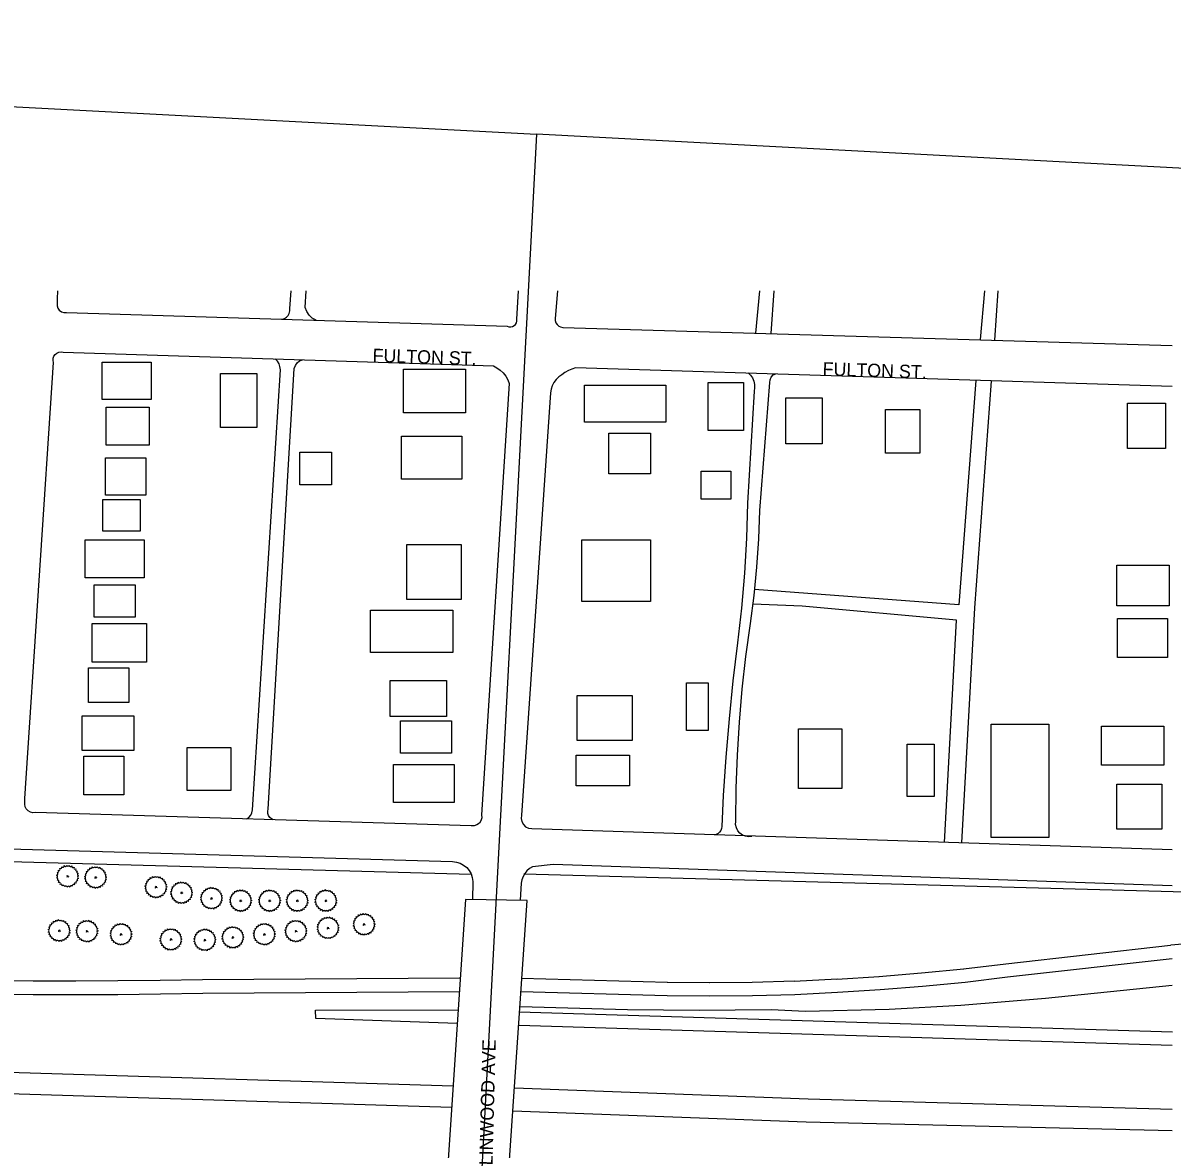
# Model space of a CAD drawing. Extents: x -9648 to 41057, y -12373 to 40276.
# Drawn here: x 13685 to 14546, y -5099 to -4256 of the extents above; entities that cross this region are included whole.
import ezdxf

# ---------------------------------------------------------------- set-up
doc = ezdxf.new("R2010")
doc.units = 0
for name, color, linetype in [('Default', 7, 'Continuous'), ('SC_Scratch1', 7, 'Continuous'), ('SH_Data', 7, 'Continuous')]:
    doc.layers.add(name, color=color, linetype=linetype)

# ---------------------------------------------------------------- blocks, each defined once
blk = doc.blocks.new('15_PIN')
at = {"layer": 'Default'}
for p, q in [((-2.8, 0), (2.8, 0)), ((0, 2.8), (0, -2.8))]:
    blk.add_line(p, q, dxfattribs=at)
for centre, start, end in [((-25.5, 4.5), 275.99, 64.01), ((-25.9, -1.5), 289.3234, 77.3433), ((-23.8, 10.3), 262.6567, 50.6766), ((-20.8, 15.5), 249.3234, 37.3433), ((-16.7, 19.8), 235.99, 24.01), ((-11.6, 23.2), 222.6567, 10.6766), ((-6, 25.2), 209.3234, 357.3433), ((0, 25.9), 195.99, 344.01), ((6, 25.2), 182.6567, 330.6766), ((11.6, 23.2), 169.3234, 317.3433), ((16.7, 19.8), 155.99, 304.01), ((20.8, 15.5), 142.6567, 290.6766), ((23.8, 10.3), 129.3234, 277.3433), ((25.5, 4.5), 115.99, 264.01), ((25.9, -1.5), 102.6567, 250.6766), ((-24.8, -7.4), 302.6567, 90.6766), ((-22.4, -13), 315.99, 104.01), ((-18.8, -17.8), 329.3234, 117.3433), ((-14.2, -21.6), 342.6567, 130.6766), ((-8.9, -24.3), 355.99, 144.01), ((-3, -25.7), 9.3234, 157.3433), ((3, -25.7), 22.6567, 170.6766), ((8.9, -24.3), 35.99, 184.01), ((14.2, -21.6), 49.3234, 197.3433), ((18.8, -17.8), 62.6567, 210.6767), ((22.4, -13), 75.99, 224.01), ((24.8, -7.4), 89.3234, 237.3433)]:
    blk.add_arc(centre, 3.05, start, end, dxfattribs=at)

msp = doc.modelspace()

# ---------------------------------------------------------------- linework, layer by layer
at = {"layer": 'SC_Scratch1'}
for p, q in [((12492.94, -4255.51), (14069.83, -4338.81)), ((14069.83, -4338.81), (13988.59, -5876.66)), ((14069.83, -4338.81), (13988.59, -5876.66)), ((14069.83, -4338.81), (13988.59, -5876.66)), ((15927.4, -4436.94), (14069.83, -4338.81))]:
    msp.add_line(p, q, dxfattribs=at)
at = {"layer": 'SH_Data'}
for p, q in [((13710.88, -4456.26), (13710.48, -4462.06)), ((13885.08, -4469.46), (13885.88, -4456.26)), ((13896.48, -4468.66), (13897.08, -4456.26)), ((14055.08, -4477.46), (14056.28, -4456.26)), ((14085.48, -4456.26), (14083.88, -4476.86)), ((14234.28, -4487.86), (14237.08, -4456.26)), ((14247.68, -4456.26), (14245.48, -4488.16)), ((14405.48, -4456.26), (14402.28, -4492.76)), ((14413.28, -4493.06), (14415.68, -4456.26)), ((13710.48, -4462.06), (13710.68, -4465.46)), ((13710.68, -4465.46), (13710.58, -4467.36)), ((13710.58, -4467.36), (13711.08, -4469.26)), ((13897.58, -4471.76), (13896.48, -4468.66)), ((13711.08, -4469.26), (13712.18, -4470.76)), ((13712.18, -4470.76), (13713.78, -4471.96)), ((13713.78, -4471.96), (13715.58, -4472.46)), ((13715.58, -4472.46), (13717.48, -4472.46)), ((13717.48, -4472.46), (14047.88, -4482.66)), ((13879.08, -4477.46), (13880.88, -4476.96)), ((13880.88, -4476.96), (13882.38, -4475.96)), ((13882.38, -4475.96), (13883.68, -4474.66)), ((13883.68, -4474.66), (13884.58, -4473.06)), ((13884.58, -4473.06), (13885.08, -4471.26)), ((13885.08, -4471.26), (13885.08, -4469.46)), ((13899.38, -4474.46), (13897.58, -4471.76)), ((13901.78, -4476.66), (13899.38, -4474.46)), ((13904.58, -4478.26), (13901.78, -4476.66)), ((14055.08, -4478.86), (14055.08, -4477.46)), ((14083.88, -4476.86), (14083.88, -4478.46)), ((14047.88, -4482.66), (14049.18, -4483.06)), ((14049.18, -4483.06), (14050.58, -4483.16)), ((14050.58, -4483.16), (14051.88, -4482.86)), ((14051.88, -4482.86), (14053.08, -4482.26)), ((14053.08, -4482.26), (14054.08, -4481.36)), ((14054.08, -4481.36), (14054.78, -4480.16)), ((14054.78, -4480.16), (14055.08, -4478.86)), ((14083.88, -4478.46), (14084.38, -4480.06)), ((14084.38, -4480.06), (14085.28, -4481.46)), ((14085.28, -4481.46), (14086.48, -4482.56)), ((14086.48, -4482.56), (14087.88, -4483.26)), ((14087.88, -4483.26), (14089.48, -4483.66)), ((14089.48, -4483.66), (14546.08, -4497.06)), ((13709.18, -4503.76), (13710.38, -4502.76)), ((13710.38, -4502.76), (13711.88, -4502.06)), ((13711.88, -4502.06), (13713.48, -4501.86)), ((13713.48, -4501.86), (13715.08, -4502.06)), ((13715.08, -4502.06), (14037.48, -4512.46)), ((13686.28, -4836.46), (13707.88, -4509.86)), ((13707.58, -4508.26), (13707.68, -4506.66)), ((13707.88, -4509.86), (13707.58, -4508.26)), ((13707.68, -4506.66), (13708.18, -4505.16)), ((13708.18, -4505.16), (13709.18, -4503.76)), ((13875.68, -4508.86), (13874.08, -4507.16)), ((13876.88, -4510.76), (13875.68, -4508.86)), ((13877.58, -4512.96), (13876.88, -4510.76)), ((13888.28, -4514.26), (13889.08, -4512.06)), ((13889.08, -4512.06), (13890.38, -4510.06)), ((13890.38, -4510.06), (13892.28, -4508.66)), ((13892.28, -4508.66), (13894.48, -4507.86)), ((13856.88, -4845.06), (13877.88, -4515.26)), ((13868.68, -4844.46), (13888.28, -4514.26)), ((13877.88, -4515.26), (13877.58, -4512.96)), ((14037.48, -4512.46), (14040.18, -4513.86)), ((14040.18, -4513.86), (14042.68, -4515.56)), ((14042.68, -4515.56), (14044.88, -4517.66)), ((14044.88, -4517.66), (14046.78, -4520.16)), ((14046.78, -4520.16), (14048.28, -4522.76)), ((14086.48, -4520.66), (14084.48, -4522.66)), ((14088.68, -4519.06), (14086.48, -4520.66)), ((14091.08, -4517.36), (14088.68, -4519.06)), ((14093.68, -4515.96), (14091.08, -4517.36)), ((14096.28, -4514.76), (14093.68, -4515.96)), ((14099.08, -4513.86), (14096.28, -4514.76)), ((14546.08, -4527.86), (14099.08, -4513.86)), ((14228.38, -4517.56), (14230.18, -4519.36)), ((14230.18, -4519.36), (14231.58, -4521.46)), ((14244.88, -4522.76), (14245.78, -4520.76)), ((14245.78, -4520.76), (14247.18, -4519.16)), ((14247.18, -4519.16), (14249.18, -4518.26)), ((14049.28, -4525.66), (14028.68, -4848.86)), ((14048.28, -4522.76), (14049.28, -4525.66)), ((14081.58, -4527.36), (14080.78, -4529.96)), ((14082.88, -4524.86), (14081.58, -4527.36)), ((14084.48, -4522.66), (14082.88, -4524.86)), ((14231.58, -4521.46), (14232.58, -4523.76)), ((14232.58, -4523.76), (14233.18, -4526.26)), ((14233.28, -4528.76), (14232.88, -4531.26)), ((14233.18, -4526.26), (14233.28, -4528.76)), ((14237.28, -4620.66), (14244.68, -4524.86)), ((14244.68, -4524.86), (14244.88, -4522.76)), ((14399.08, -4523.46), (14386.28, -4691.46)), ((14398.28, -4693.66), (14410.68, -4523.76)), ((14080.28, -4532.66), (14058.48, -4849.06)), ((14080.78, -4529.96), (14080.28, -4532.66)), ((14232.88, -4531.26), (14227.88, -4615.26)), ((14227.88, -4615.26), (14227.18, -4641.46)), ((14236.48, -4641.96), (14237.28, -4620.66)), ((14227.18, -4641.46), (14225.78, -4667.66)), ((14234.98, -4663.16), (14236.48, -4641.96)), ((14232.88, -4684.36), (14234.98, -4663.16)), ((14225.78, -4667.66), (14223.48, -4693.86)), ((14230.08, -4705.46), (14232.88, -4684.36)), ((14386.28, -4691.46), (14233.28, -4679.86)), ((14268.98, -4692.46), (14231.98, -4691.06)), ((14384.68, -4702.86), (14268.98, -4692.46)), ((14223.48, -4693.86), (14220.48, -4719.86)), ((14388.68, -4869.86), (14398.28, -4693.66)), ((14226.78, -4730.06), (14230.08, -4705.46)), ((14375.68, -4869.46), (14384.68, -4702.86)), ((14220.48, -4719.86), (14216.98, -4748.36)), ((14223.98, -4754.66), (14226.78, -4730.06)), ((14216.98, -4748.36), (14214.08, -4776.96)), ((14221.88, -4779.36), (14223.98, -4754.66)), ((14214.08, -4776.96), (14211.58, -4805.56)), ((14220.38, -4804.06), (14221.88, -4779.36)), ((14219.38, -4828.86), (14220.38, -4804.06)), ((14211.58, -4805.56), (14209.68, -4834.26)), ((14219.08, -4853.66), (14219.38, -4828.86)), ((13686.28, -4840.66), (13686.28, -4836.46)), ((14209.68, -4834.26), (14208.68, -4857.46)), ((13686.58, -4842.66), (13686.28, -4840.66)), ((13687.48, -4844.36), (13686.58, -4842.66)), ((13688.88, -4845.86), (13687.48, -4844.36)), ((13690.58, -4846.76), (13688.88, -4845.86)), ((13692.48, -4847.26), (13690.58, -4846.76)), ((13694.48, -4847.06), (13692.48, -4847.26)), ((14020.88, -4857.06), (13694.48, -4847.06)), ((13855.68, -4849.06), (13856.58, -4847.16)), ((13856.58, -4847.16), (13856.88, -4845.06)), ((13868.38, -4846.06), (13868.68, -4844.46)), ((13868.58, -4847.66), (13868.38, -4846.06)), ((13869.08, -4849.26), (13868.58, -4847.66)), ((12887.08, -4851.86), (14006.88, -4883.86)), ((13852.58, -4851.86), (13854.28, -4850.66)), ((13854.28, -4850.66), (13855.68, -4849.06)), ((13869.98, -4850.66), (13869.08, -4849.26)), ((13871.18, -4851.76), (13869.98, -4850.66)), ((13872.58, -4852.56), (13871.18, -4851.76)), ((14025.18, -4856.36), (14023.08, -4857.06)), ((14026.98, -4854.96), (14025.18, -4856.36)), ((14028.18, -4853.16), (14026.98, -4854.96)), ((14028.78, -4851.06), (14028.18, -4853.16)), ((14028.68, -4848.86), (14028.78, -4851.06)), ((14058.48, -4849.06), (14058.28, -4851.46)), ((14058.28, -4851.46), (14058.78, -4853.86)), ((14058.78, -4853.86), (14059.98, -4855.96)), ((14059.98, -4855.96), (14061.68, -4857.66)), ((14218.98, -4856.06), (14219.08, -4853.66)), ((14219.58, -4858.46), (14218.98, -4856.06)), ((12877.89, -4861.38), (14020.89, -4893.32)), ((14023.08, -4857.06), (14020.88, -4857.06)), ((14061.68, -4857.66), (14063.88, -4858.66)), ((14063.88, -4858.66), (14066.28, -4859.06)), ((14066.28, -4859.06), (14546.08, -4874.86)), ((14204.48, -4863.56), (14202.98, -4863.96)), ((14205.88, -4862.76), (14204.48, -4863.56)), ((14206.98, -4861.76), (14205.88, -4862.76)), ((14207.88, -4860.46), (14206.98, -4861.76)), ((14208.48, -4858.96), (14207.88, -4860.46)), ((14208.68, -4857.46), (14208.48, -4858.96)), ((14220.68, -4860.66), (14219.58, -4858.46)), ((14222.18, -4862.46), (14220.68, -4860.66)), ((14224.18, -4863.96), (14222.18, -4862.46)), ((14226.48, -4864.86), (14224.18, -4863.96)), ((14228.88, -4865.16), (14226.48, -4864.86)), ((14231.28, -4864.96), (14228.88, -4865.16)), ((14006.88, -4883.86), (14009.78, -4884.16)), ((14009.78, -4884.16), (14012.58, -4884.96)), ((14012.58, -4884.96), (14015.18, -4886.36)), ((14015.18, -4886.36), (14017.48, -4888.16)), ((14017.48, -4888.16), (14019.38, -4890.36)), ((14019.38, -4890.36), (14020.78, -4892.96)), ((14062.68, -4890.66), (14061.08, -4892.66)), ((14064.68, -4889.06), (14062.68, -4890.66)), ((14066.88, -4887.66), (14064.68, -4889.06)), ((14082.28, -4886.06), (14066.88, -4887.66)), ((14546.08, -4902.06), (14082.28, -4886.06)), ((14020.78, -4892.96), (14021.68, -4895.76)), ((14021.68, -4895.76), (14022.08, -4898.66)), ((14022.08, -4898.66), (14021.88, -4912.36)), ((14058.78, -4897.36), (14058.28, -4899.86)), ((14059.78, -4894.96), (14058.78, -4897.36)), ((14061.08, -4892.66), (14059.78, -4894.96)), ((14060.29, -4893.04), (14898.14, -4915.82)), ((14058.28, -4899.86), (14057.68, -4912.76)), ((14016.68, -4912.26), (13996.68, -5208.46)), ((14062.88, -4912.86), (14016.68, -4912.26)), ((14042.68, -5209.26), (14062.88, -4912.86)), ((14973.21, -4909.3), (14545.21, -4946.5)), ((14421.56, -4960.32), (14544.96, -4946.52)), ((14422.68, -4970.26), (14546.08, -4956.46)), ((14326.46, -4969.79), (14358.36, -4967.19)), ((14358.21, -4967.21), (14390.01, -4964.11)), ((14389.79, -4964.13), (14421.49, -4960.33)), ((13692.8, -4973.46), (13412.6, -4969.86)), ((13724.48, -4973.46), (13692.68, -4973.46)), ((13756.11, -4973.26), (13724.41, -4973.46)), ((13787.88, -4972.96), (13756.08, -4973.26)), ((13819.52, -4972.46), (13787.82, -4972.96)), ((14012, -4971.06), (13819.6, -4972.46)), ((14058.45, -4971.07), (14167.95, -4974.07)), ((14167.77, -4974.06), (14199.67, -4974.36)), ((14199.48, -4974.36), (14231.48, -4974.06)), ((14231.33, -4974.06), (14263.23, -4973.26)), ((14263.01, -4973.27), (14295.01, -4971.77)), ((14294.85, -4971.78), (14326.65, -4969.78)), ((14359.18, -4977.16), (14390.98, -4974.06)), ((14390.98, -4974.06), (14422.68, -4970.26)), ((14451.28, -4986.16), (14546.08, -4976.46)), ((13412.48, -4979.86), (13692.68, -4983.46)), ((13692.68, -4983.46), (13724.48, -4983.46)), ((13724.48, -4983.46), (13756.18, -4983.26)), ((13756.18, -4983.26), (13787.98, -4982.96)), ((13787.98, -4982.96), (13819.68, -4982.46)), ((13819.68, -4982.46), (14012.08, -4981.06)), ((14058.18, -4981.06), (14167.68, -4984.06)), ((14167.68, -4984.06), (14199.58, -4984.36)), ((14199.58, -4984.36), (14231.58, -4984.06)), ((14231.58, -4984.06), (14263.48, -4983.26)), ((14263.48, -4983.26), (14295.48, -4981.76)), ((14295.48, -4981.76), (14327.28, -4979.76)), ((14327.28, -4979.76), (14359.18, -4977.16)), ((14057.48, -4992.26), (14138.08, -4994.66)), ((14334.18, -4994.46), (14387.88, -4991.46)), ((14387.88, -4991.46), (14451.28, -4986.16)), ((13904.28, -4995.06), (14011.08, -4994.86)), ((13904.48, -5001.46), (13904.28, -4995.06)), ((14010.38, -5005.06), (13904.48, -5001.46)), ((14056.79, -4996.27), (14546.39, -5011.47)), ((14138.08, -4994.66), (14164.98, -4994.96)), ((14164.98, -4994.96), (14191.88, -4995.06)), ((14191.88, -4995.06), (14218.78, -4994.96)), ((14218.78, -4994.96), (14245.68, -4994.66)), ((14245.68, -4994.66), (14271.48, -4995.86)), ((14271.48, -4995.86), (14334.18, -4994.46)), ((14056.48, -5006.26), (14546.08, -5021.46)), ((13531.08, -5037.06), (14007.28, -5051.86)), ((13530.28, -5053.06), (14006.18, -5067.86)), ((14053.28, -5053.26), (14273.28, -5061.66)), ((14273.28, -5061.66), (14546.08, -5069.26)), ((14052.18, -5070.46), (14271.88, -5078.66)), ((14271.88, -5078.66), (14546.08, -5085.26))]:
    msp.add_line(p, q, dxfattribs=at)
for points in [[(13744.21, -4509.56), (13781.16, -4509.56), (13781.16, -4537.55), (13744.21, -4537.55)], [(13832.89, -4518.01), (13860.33, -4518.01), (13860.33, -4558.67), (13832.89, -4558.67)], [(13970.12, -4514.85), (14016.57, -4514.85), (14016.57, -4547.58), (13970.12, -4547.58)], [(14105.72, -4526.89), (14166.68, -4526.89), (14166.68, -4554.67), (14105.72, -4554.67)], [(14198.51, -4524.86), (14224.92, -4524.86), (14224.92, -4560.77), (14198.51, -4560.77)], [(14256.76, -4536.38), (14283.85, -4536.38), (14283.85, -4570.93), (14256.76, -4570.93)], [(13747.38, -4543.36), (13779.58, -4543.36), (13779.58, -4571.87), (13747.38, -4571.87)], [(14331.26, -4545.18), (14356.99, -4545.18), (14356.99, -4577.7), (14331.26, -4577.7)], [(14512.77, -4540.44), (14541.22, -4540.44), (14541.22, -4574.32), (14512.77, -4574.32)], [(14124.01, -4562.8), (14155.16, -4562.8), (14155.16, -4593.29), (14124.01, -4593.29)], [(13968.54, -4565.01), (14013.93, -4565.01), (14013.93, -4597.21), (13968.54, -4597.21)], [(13892.53, -4577.15), (13916.28, -4577.15), (13916.28, -4601.44), (13892.53, -4601.44)], [(13746.85, -4581.37), (13776.94, -4581.37), (13776.94, -4609.36), (13746.85, -4609.36)], [(14193.09, -4591.26), (14215.44, -4591.26), (14215.44, -4612.26), (14193.09, -4612.26)], [(13744.74, -4612.53), (13772.71, -4612.53), (13772.71, -4636.29), (13744.74, -4636.29)], [(13731.54, -4642.62), (13775.88, -4642.62), (13775.88, -4671.14), (13731.54, -4671.14)], [(13972.76, -4646.32), (14013.41, -4646.32), (14013.41, -4687.5), (13972.76, -4687.5)], [(14103.69, -4642.75), (14155.16, -4642.75), (14155.16, -4688.82), (14103.69, -4688.82)], [(14504.64, -4661.72), (14543.93, -4661.72), (14543.93, -4692.2), (14504.64, -4692.2)], [(13738.4, -4676.42), (13769.02, -4676.42), (13769.02, -4700.7), (13738.4, -4700.7)], [(13945.31, -4695.42), (14007.07, -4695.42), (14007.07, -4727.1), (13945.31, -4727.1)], [(13736.82, -4705.46), (13777.46, -4705.46), (13777.46, -4734.5), (13736.82, -4734.5)], [(14505.32, -4701.69), (14542.57, -4701.69), (14542.57, -4730.82), (14505.32, -4730.82)], [(13734.18, -4738.72), (13764.27, -4738.72), (13764.27, -4764.59), (13734.18, -4764.59)], [(13960.09, -4748.22), (14002.32, -4748.22), (14002.32, -4775.15), (13960.09, -4775.15)], [(14182.25, -4749.79), (14198.51, -4749.79), (14198.51, -4785.7), (14182.25, -4785.7)], [(14100.3, -4759.28), (14141.62, -4759.28), (14141.62, -4793.15), (14100.3, -4793.15)], [(13729.43, -4774.63), (13767.96, -4774.63), (13767.96, -4800.5), (13729.43, -4800.5)], [(13968.01, -4778.32), (14006.02, -4778.32), (14006.02, -4802.61), (13968.01, -4802.61)], [(14266.24, -4784.35), (14298.75, -4784.35), (14298.75, -4829.06), (14266.24, -4829.06)], [(14410.5, -4780.96), (14453.85, -4780.96), (14453.85, -4865.65), (14410.5, -4865.65)], [(14493.13, -4782.31), (14539.86, -4782.31), (14539.86, -4811.45), (14493.13, -4811.45)], [(14347.51, -4795.86), (14367.83, -4795.86), (14367.83, -4835.16), (14347.51, -4835.16)], [(13730.49, -4804.72), (13760.57, -4804.72), (13760.57, -4833.76), (13730.49, -4833.76)], [(13808.08, -4798.39), (13840.8, -4798.39), (13840.8, -4830.59), (13808.08, -4830.59)], [(14099.62, -4803.99), (14139.58, -4803.99), (14139.58, -4827.03), (14099.62, -4827.03)], [(13962.73, -4811.06), (14008.13, -4811.06), (14008.13, -4839.57), (13962.73, -4839.57)], [(14504.64, -4825.68), (14538.51, -4825.68), (14538.51, -4859.55), (14504.64, -4859.55)]]:
    msp.add_lwpolyline(points, close=True, dxfattribs=at)

# ---------------------------------------------------------------- block references
at = {"layer": 'SH_Data', "xscale": 0.32808397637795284, "yscale": 0.32808397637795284, "rotation": 64.61472397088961}
for p in [(13718.43, -4894.74), (13739.41, -4895.64), (13784.64, -4902.89), (13803.82, -4907.16), (13826.27, -4911.28), (13848.12, -4913.08), (13869.84, -4913.09), (13890.53, -4913.09), (13911.98, -4913.09), (13712.14, -4935.53), (13732.96, -4935.94), (13889.55, -4935.89), (13913.59, -4933.5), (13940.59, -4930.83), (13758.46, -4938.27), (13795.84, -4942.13), (13821.26, -4942.48), (13842.25, -4940.58), (13865.84, -4938.24)]:
    msp.add_blockref('15_PIN', p, dxfattribs=at)

# ---------------------------------------------------------------- texts
at = {"layer": 'SC_Scratch1'}
for s, rotation, p in [('FULTON ST.', 358.15234, (13946.81, -4509.46)), ('FULTON ST.', 358.20609, (14284.11, -4519.58)), ('LINWOOD AVE', 88.50218, (14036.84, -5111.46))]:
    msp.add_text(s, height=10, rotation=rotation, dxfattribs=at).set_placement(p)

doc.saveas('drawing.dxf')
